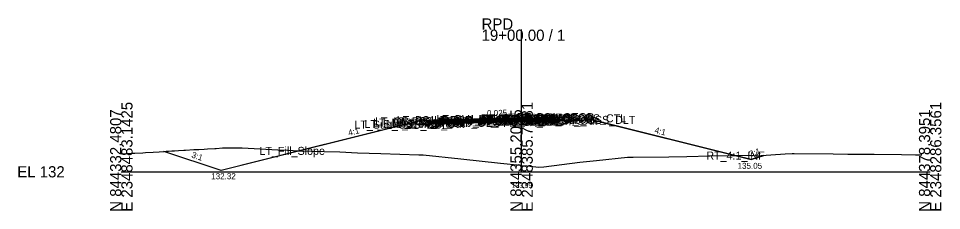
# Model space of a CAD drawing. Extents: x -26 to 2348536, y -510 to 844755.
# Drawn here: x -25.7 to 204.9, y 3990.3 to 4038.3 of the extents above; entities that cross this region are included whole.
import ezdxf

# ---------------------------------------------------------------- set-up
doc = ezdxf.new("R2010")
doc.units = 0
for name, color, linetype in [('Default', 7, 'Continuous'), ('Exist Cross Section Cell', 7, 'Continuous'), ('Exist XS Center Line Elevation Label', 7, 'Continuous'), ('Exist XS Ground Line', 7, 'Continuous'), ('Prop CMT Pvmt Course 1', 7, 'Continuous'), ('Prop CMT Pvmt Course 2', 7, 'Continuous'), ('Prop CMT Pvmt Course 3', 7, 'Continuous'), ('Prop CMT Pvmt Surface', 7, 'Continuous'), ('Prop CMT Pvmt Surface Shoulder', 7, 'Continuous'), ('Prop CMT Shld Paved Course 1', 7, 'Continuous'), ('Prop CMT Shld Paved Course 2', 7, 'Continuous'), ('Prop CMT Shld Paved Course 3', 7, 'Continuous'), ('Prop CMT Slope Grass', 7, 'Continuous'), ('Prop CMT Subgrade Earthwork', 7, 'Continuous'), ('Prop XS Ditch Standard Text', 7, 'Continuous'), ('Prop XS Earthwork Shape', 7, 'Continuous'), ('Prop XS SE Text', 7, 'Continuous'), ('Prop XS Side Slope Text', 7, 'Continuous'), ('Scratch_Level_0', 7, 'Continuous')]:
    doc.layers.add(name, color=color, linetype=linetype)

msp = doc.modelspace()

# ---------------------------------------------------------------- linework, layer by layer
at = {"layer": 'Exist Cross Section Cell'}
for p, q in [((100, 4000), (100, 4035.55)), ((0, 4000), (100, 4000)), ((100, 4000), (202.07, 4000))]:
    msp.add_line(p, q, dxfattribs=at)
at = {"layer": 'Exist XS Ground Line'}
msp.add_lwpolyline([(0, 4004.46), (2.76, 4004.62), (3.37, 4004.65), (5.37, 4004.77), (6.04, 4004.81), (7.96, 4004.92), (9.44, 4005.01), (10.52, 4005.07), (11.24, 4005.13), (11.82, 4005.18), (12.6, 4005.2), (13.33, 4005.23), (14.27, 4005.29), (15.63, 4005.38), (16.06, 4005.41), (18.16, 4005.54), (19.39, 4005.61), (20.72, 4005.69), (21.57, 4005.74), (23.33, 4005.84), (23.69, 4005.86), (25.29, 4005.96), (25.85, 4005.99), (27.87, 4006.01), (28.56, 4006.02), (30.16, 4006), (39.11, 4005.51), (41.49, 4005.38), (44.33, 4005.21), (50.66, 4005.07), (54.6, 4004.95), (58.99, 4004.78), (64.87, 4004.61), (74.33, 4004.27), (75.14, 4004.25), (75.45, 4004.21), (84.85, 4003.26), (94.75, 4002.13), (99.64, 4001.63), (100, 4001.59), (101.37, 4001.45), (104.31, 4001.17), (105.58, 4001.26), (114.57, 4002.39), (118.68, 4002.84), (126.48, 4003.64), (127.91, 4003.67), (136.75, 4003.75), (141.3, 4003.83), (147.02, 4003.98), (154.7, 4004.08), (157.29, 4004.12), (158.69, 4003.98), (165.81, 4004.48), (167.56, 4004.56), (168.09, 4004.54), (177.83, 4004.45), (181.49, 4004.39), (188.1, 4004.38), (194.88, 4004.33), (198.37, 4004.28), (200, 4004.27)], dxfattribs=at)
at = {"layer": 'Prop CMT Pvmt Course 1'}
for p, q in [((100, 4013.46), (88, 4013.16)), ((88, 4012.91), (100, 4013.21)), ((88, 4013.16), (88, 4012.91)), ((100, 4013.46), (104, 4013.56)), ((100, 4013.21), (100, 4013.46)), ((100, 4013.21), (100, 4013.46)), ((100, 4013.21), (100, 4013.33)), ((100, 4013.33), (100, 4013.33)), ((100, 4013.33), (100, 4013.21)), ((100, 4013.21), (100, 4013.33)), ((100, 4013.33), (100, 4013.33)), ((100, 4013.33), (100, 4013.21)), ((104, 4013.31), (100, 4013.21)), ((100, 4013.21), (100, 4013.21)), ((100, 4013.21), (100, 4013.21)), ((104, 4013.56), (104, 4013.31))]:
    msp.add_line(p, q, dxfattribs=at)
at = {"layer": 'Prop CMT Pvmt Course 2'}
for p, q in [((100, 4013.21), (88, 4012.91)), ((88, 4012.91), (88, 4012.58)), ((88, 4012.58), (100, 4012.88)), ((100, 4013.21), (104, 4013.31)), ((100, 4012.88), (100, 4013.21)), ((100, 4012.88), (100, 4013.21)), ((104, 4012.98), (100, 4012.88)), ((104, 4013.31), (104, 4012.98))]:
    msp.add_line(p, q, dxfattribs=at)
at = {"layer": 'Prop CMT Pvmt Course 3'}
for p, q in [((100, 4012.88), (88, 4012.58)), ((88, 4012.58), (88, 4012.24)), ((88, 4012.24), (100, 4012.54)), ((100, 4012.88), (104, 4012.98)), ((100, 4012.54), (100, 4012.88)), ((100, 4012.54), (100, 4012.88)), ((104, 4012.64), (100, 4012.54)), ((104, 4012.98), (104, 4012.64))]:
    msp.add_line(p, q, dxfattribs=at)
at = {"layer": 'Prop CMT Pvmt Surface'}
for q in [(88, 4013.16), (104, 4013.56)]:
    msp.add_line((100, 4013.46), q, dxfattribs=at)
at = {"layer": 'Prop CMT Pvmt Surface Shoulder'}
for p, q in [((88, 4013.16), (78, 4012.91)), ((104, 4013.56), (108, 4013.66))]:
    msp.add_line(p, q, dxfattribs=at)
at = {"layer": 'Prop CMT Shld Paved Course 1'}
for p, q in [((78, 4012.91), (77.74, 4012.65)), ((77.74, 4012.65), (88, 4012.91)), ((88, 4013.16), (78, 4012.91)), ((88, 4012.91), (88, 4013.16)), ((104, 4013.56), (108, 4013.66)), ((104, 4013.31), (104, 4013.56)), ((108.24, 4013.41), (104, 4013.31)), ((108, 4013.66), (108.24, 4013.41))]:
    msp.add_line(p, q, dxfattribs=at)
at = {"layer": 'Prop CMT Shld Paved Course 2'}
for p, q in [((77.74, 4012.65), (77.4, 4012.31)), ((77.4, 4012.31), (88, 4012.58)), ((88, 4012.91), (77.74, 4012.65)), ((88, 4012.58), (88, 4012.91)), ((104, 4013.31), (108.24, 4013.41)), ((104, 4012.98), (104, 4013.31)), ((108.57, 4013.09), (104, 4012.98)), ((108.24, 4013.41), (108.57, 4013.09))]:
    msp.add_line(p, q, dxfattribs=at)
at = {"layer": 'Prop CMT Shld Paved Course 3'}
for p, q in [((88, 4012.58), (77.4, 4012.31)), ((88, 4012.24), (88, 4012.58)), ((104, 4012.98), (108.57, 4013.09)), ((104, 4012.64), (104, 4012.98)), ((109.39, 4012.78), (104, 4012.64)), ((108.57, 4013.09), (109.07, 4013.1)), ((109.07, 4013.1), (109.39, 4012.78)), ((76.9, 4012.3), (76.56, 4011.96)), ((76.56, 4011.96), (88, 4012.24)), ((77.4, 4012.31), (76.9, 4012.3))]:
    msp.add_line(p, q, dxfattribs=at)
at = {"layer": 'Prop CMT Slope Grass'}
for p, q in [((74, 4012.59), (24.92, 4000.32)), ((78, 4012.91), (74, 4012.59)), ((108, 4013.66), (116, 4013.38)), ((116, 4013.38), (157.32, 4003.05)), ((24.92, 4000.32), (10.64, 4005.08)), ((157.32, 4003.05), (160.48, 4004.1))]:
    msp.add_line(p, q, dxfattribs=at)
at = {"layer": 'Prop CMT Subgrade Earthwork'}
for p, q in [((100, 4012.54), (88, 4012.24)), ((100, 4012.54), (104, 4012.64)), ((104, 4012.64), (109.39, 4012.78)), ((109.39, 4012.78), (117.59, 4012.98)), ((76.56, 4011.96), (70.9, 4011.81)), ((88, 4012.24), (76.56, 4011.96))]:
    msp.add_line(p, q, dxfattribs=at)
at = {"layer": 'Prop XS Earthwork Shape'}
for points in [[(70.9, 4011.81), (44.46, 4005.2), (50.66, 4005.07), (54.6, 4004.95), (58.99, 4004.78), (64.87, 4004.61), (74.33, 4004.27), (75.14, 4004.25), (75.45, 4004.21), (84.85, 4003.26), (94.75, 4002.13), (99.64, 4001.63), (100, 4001.59), (101.37, 4001.45), (104.31, 4001.17), (105.58, 4001.26), (114.57, 4002.39), (118.68, 4002.84), (126.48, 4003.64), (127.91, 4003.67), (136.75, 4003.75), (141.3, 4003.83), (147.02, 4003.98), (153.27, 4004.06), (117.59, 4012.98), (109.39, 4012.78), (104, 4012.64), (100, 4012.54), (88, 4012.24), (76.56, 4011.96)], [(11.24, 4005.13), (11.82, 4005.18), (12.6, 4005.2), (13.33, 4005.23), (14.27, 4005.29), (15.63, 4005.38), (16.06, 4005.41), (18.16, 4005.54), (19.39, 4005.61), (20.72, 4005.69), (21.57, 4005.74), (23.33, 4005.84), (23.69, 4005.86), (25.29, 4005.96), (25.85, 4005.99), (27.87, 4006.01), (28.56, 4006.02), (30.16, 4006), (39.11, 4005.51), (41.49, 4005.38), (44.33, 4005.21), (44.46, 4005.2), (24.92, 4000.32), (10.64, 4005.08)], [(154.7, 4004.08), (157.29, 4004.12), (158.69, 4003.98), (160.48, 4004.1), (157.32, 4003.05), (153.27, 4004.06)]]:
    msp.add_lwpolyline(points, close=True, dxfattribs=at)

# ---------------------------------------------------------------- texts
at = {"layer": 'Default'}
msp.add_text('-', height=0.0001, dxfattribs=at).set_placement((0, 4000))
at = {"layer": 'Exist Cross Section Cell'}
for s, p in [('RPD', (90, 4035.55)), ('19+00.00 / 1', (90, 4032.75)), ('EL 132', (-26, 3998.6))]:
    msp.add_text(s, height=2.8, dxfattribs=at).set_placement(p)
for s, p in [('E 2348483.1425', (2.8, 3990)), ('E 2348385.7581', (102.8, 3990)), ('E 2348286.3561', (204.87, 3990)), ('N 844332.4807', (0, 3990)), ('N 844355.2025', (100, 3990)), ('N 844378.3951', (202.07, 3990))]:
    msp.add_text(s, height=2.8, rotation=90, dxfattribs=at).set_placement(p)
at = {"layer": 'Exist XS Center Line Elevation Label'}
msp.add_text('133.59', height=1.2, dxfattribs=at).set_placement((97.55, 3995.99))
at = {"layer": 'Prop XS Ditch Standard Text'}
for s, p in [('135.05', (153.95, 4000.74)), ('132.32', (22.46, 3998.15))]:
    msp.add_text(s, height=1.5, dxfattribs=at).set_placement(p)
at = {"layer": 'Prop XS SE Text'}
msp.add_text('0.025', height=1.5, rotation=1.4321, dxfattribs=at).set_placement((91.38, 4013.9))
at = {"layer": 'Prop XS Side Slope Text'}
for s, rotation, p in [('4:1', 14.0362, (56.88, 4008.97)), ('4:1', 345.9638, (133.11, 4009.74)), ('3:1', 18.4349, (157.16, 4003.69)), ('3:1', 341.5651, (17.42, 4003.61))]:
    msp.add_text(s, height=1.5, rotation=rotation, dxfattribs=at).set_placement(p)
at = {"layer": 'Scratch_Level_0'}
for s, p in [('LT_Sub_OSS_DLT', (58.24, 4010.81)), ('LT_Sub_Trench_Out', (60.76, 4010.96)), ('LT_PS3_Shelf_Out', (62.89, 4011.3)), ('LT_GS_OS_CTL', (63.37, 4011.59)), ('LT_PS3_OEOP', (67.64, 4011.31)), ('LT_PS2_OEOP', (67.98, 4011.65)), ('LT_PS1_OEOP', (68.8, 4011.91)), ('LT_Sub_OEOT', (78.08, 4011.24)), ('LT_PV2_OEOT', (78.17, 4011.91)), ('LT_PV3_OEOT', (78.17, 4011.58)), ('LT_PV1_OEOT', (78.74, 4012.16)), ('RT_Sub_OEEOP', (89.17, 4011.54)), ('LT_Sub_OEEOP', (89.21, 4011.54)), ('RT_PV2_OEEOP', (89.26, 4012.21)), ('RT_PV3_OEEOP', (89.26, 4011.88)), ('LT_PV2_OEEOP', (89.31, 4012.21)), ('LT_PV3_OEEOP', (89.31, 4011.88)), ('RT_PV1_OEEOP', (89.83, 4012.33)), ('LT_PV1_OEEOP', (89.87, 4012.33)), ('RT_PV2_IEEOP', (89.91, 4012.21)), ('LT_PV2_IEEOP', (89.95, 4012.21)), ('RT_PV1_IEEOP', (90.47, 4012.33)), ('LT_PV1_IEEOP', (90.52, 4012.33)), ('RT_Sub_Trench_Out', (93.55, 4011.78)), ('PV2_PGL', (93.91, 4012.21)), ('RT_Sub_OEOT', (94.03, 4011.64)), ('RT_PV2_OEOT', (94.13, 4012.31)), ('RT_PV3_OEOT', (94.13, 4011.98)), ('PV1_PGL', (94.47, 4012.46)), ('RT_PV1_OEOT', (94.69, 4012.56)), ('RT_PS3_Shelf_Out', (95.01, 4012.1)), ('RT_PS2_OEOP', (98.43, 4012.41)), ('RT_PS1_OEOP', (98.76, 4012.66)), ('RT_PS3_OEOP', (98.76, 4012.09)), ('RT_Sub_OSS_DLT', (104.94, 4011.98)), ('RT_GS_OS_CTL', (105.32, 4012.38)), ('LT_Fill_Slope', (34.52, 4004.23)), ('RT_4:1_INF', (146.15, 4003.06))]:
    msp.add_text(s, height=2, dxfattribs=at).set_placement(p)

doc.saveas('drawing.dxf')
